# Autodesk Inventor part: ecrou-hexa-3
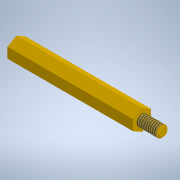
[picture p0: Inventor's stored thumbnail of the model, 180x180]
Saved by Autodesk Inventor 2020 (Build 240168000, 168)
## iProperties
Created: 2021-10
Part Number: ecrou-hexa-3
Material: Laiton, jaune doux
Document SubType Name: Modeling
Designer: bruno
Density: 7.2198 g/cm^3
Appearance: Or
Mass: 4 g
Surface Area: 10.3431 cm^2
Volume: 0.554032 cm^3
Author: bruno
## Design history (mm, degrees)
sketch "Esquisse1"
  geometry: L1 (-2.887, 0)-(-1.443, 2.5); L2 (-1.443, 2.5)-(1.443, 2.5); L3 (1.443, 2.5)-(2.887, 0); L4 (2.887, 0)-(1.443, -2.5); L5 (1.443, -2.5)-(-1.443, -2.5); L6 (-1.443, -2.5)-(-2.887, 0); C1 r 1.5 at (0, 0); 2 further points
  constraints: 12 end point, 2 coincident, 1 centre point, 13 other
  dimensions: "d0" = 5 distance between parallel lines of L2 L5; "d1" = 3 diameter of C1
extrude "Extrusion1" new body sketch "Esquisse1" distance "d2" = 35; taper "d3" = 0 deg
feature "Filetage1" dims "d4" = 17, "d5" = 0
sketch "Esquisse2"
  geometry: C1 r 1.541 at (0, 0); 1 further point
  constraints: 1 centre point, 1 coincident
extrude "Extrusion2" join sketch "Esquisse2" distance "d6" = 6; taper "d7" = 0 deg
chamfer "Chanfrein1" distance "d8" = 0.5; stored, may be unused: second distance "d9" = 2, angle "d10" = 45 deg
feature "Filetage2" dims "d11" = 5.5, "d12" = 0
node "Solide1"
